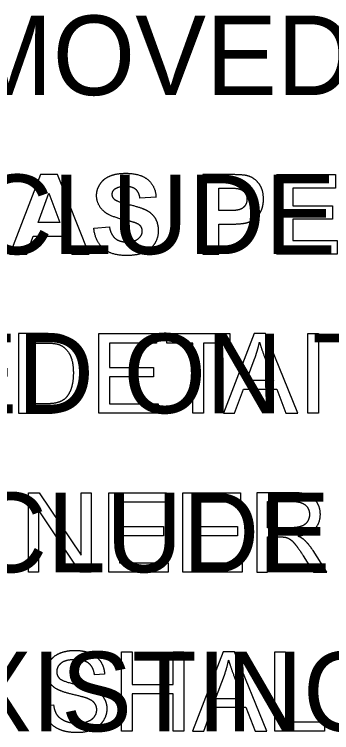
# Model space of a CAD drawing. Extents: x 12316 to 12541, y 1124 to 1850.
# Drawn here: x 12524.754 to 12525.314, y 1787.999 to 1789.263 of the extents above; entities that cross this region are included whole.
import ezdxf

# ---------------------------------------------------------------- set-up
doc = ezdxf.new("R2010")
doc.units = 0
doc.layers.add('SH_Text', color=7, linetype='Continuous')

msp = doc.modelspace()

# ---------------------------------------------------------------- linework, layer by layer
at = {"layer": 'SH_Text'}
for p, q in [((12525.0039, 1788.9412), (12524.9756, 1788.9399)), ((12524.8941, 1788.8868), (12524.9216, 1788.8895)), ((12524.9131, 1788.1018), (12524.8954, 1788.1004)), ((12524.8057, 1788.0462), (12524.8232, 1788.0477))]:
    msp.add_line(p, q, dxfattribs=at)
for points in [[(12524.8862, 1788.8412), (12524.8303, 1788.9812), (12524.8002, 1788.9812), (12524.7458, 1788.8412), (12524.7758, 1788.8412), (12524.7873, 1788.873), (12524.8433, 1788.873), (12524.8554, 1788.8412)], [(12525.2167, 1788.8412), (12525.2167, 1788.9812), (12525.3205, 1788.9812), (12525.3205, 1788.9575), (12525.2449, 1788.9575), (12525.2449, 1788.9264), (12525.3153, 1788.9264), (12525.3153, 1788.9027), (12525.2449, 1788.9027), (12525.2449, 1788.8649), (12525.3232, 1788.8649), (12525.3232, 1788.8412)], [(12524.8342, 1788.8967), (12524.796, 1788.8967), (12524.8149, 1788.9485)], [(12524.9032, 1788.5612), (12524.9032, 1788.7012), (12525.0045, 1788.7012), (12525.0045, 1788.6846), (12524.9217, 1788.6846), (12524.9217, 1788.6418), (12524.9993, 1788.6418), (12524.9993, 1788.6253), (12524.9217, 1788.6253), (12524.9217, 1788.5777), (12525.0077, 1788.5777), (12525.0077, 1788.5612)], [(12525.0689, 1788.5612), (12525.0689, 1788.6846), (12525.0228, 1788.6846), (12525.0228, 1788.7012), (12525.1338, 1788.7012), (12525.1338, 1788.6846), (12525.0874, 1788.6846), (12525.0874, 1788.5612)], [(12525.123, 1788.5612), (12525.1426, 1788.5612), (12525.158, 1788.6035), (12525.2167, 1788.6035), (12525.2329, 1788.5612), (12525.254, 1788.5612), (12525.1968, 1788.7012), (12525.1768, 1788.7012)], [(12525.2719, 1788.5612), (12525.2719, 1788.7012), (12525.2905, 1788.7012), (12525.2905, 1788.5612)], [(12524.7791, 1788.2812), (12524.7791, 1788.4212), (12524.798, 1788.4212), (12524.8717, 1788.3112), (12524.8717, 1788.4212), (12524.8894, 1788.4212), (12524.8894, 1788.2812), (12524.8704, 1788.2812), (12524.7968, 1788.3911), (12524.7968, 1788.2812)], [(12524.9209, 1788.2812), (12524.9209, 1788.4212), (12525.0222, 1788.4212), (12525.0222, 1788.4046), (12524.9394, 1788.4046), (12524.9394, 1788.3618), (12525.017, 1788.3618), (12525.017, 1788.3453), (12524.9394, 1788.3453), (12524.9394, 1788.2977), (12525.0254, 1788.2977), (12525.0254, 1788.2812)], [(12525.0514, 1788.2812), (12525.0514, 1788.4212), (12525.1527, 1788.4212), (12525.1527, 1788.4046), (12525.0699, 1788.4046), (12525.0699, 1788.3618), (12525.1475, 1788.3618), (12525.1475, 1788.3453), (12525.0699, 1788.3453), (12525.0699, 1788.2977), (12525.1559, 1788.2977), (12525.1559, 1788.2812)], [(12524.9433, 1788.0012), (12524.9433, 1788.1412), (12524.9618, 1788.1412), (12524.9618, 1788.0837), (12525.0344, 1788.0837), (12525.0344, 1788.1412), (12525.053, 1788.1412), (12525.053, 1788.0012), (12525.0344, 1788.0012), (12525.0344, 1788.0671), (12524.9618, 1788.0671), (12524.9618, 1788.0012)], [(12525.0685, 1788.0012), (12525.0882, 1788.0012), (12525.1035, 1788.0435), (12525.1623, 1788.0435), (12525.1785, 1788.0012), (12525.1996, 1788.0012), (12525.1424, 1788.1412), (12525.1223, 1788.1412)], [(12525.2136, 1788.0012), (12525.2136, 1788.1412), (12525.2321, 1788.1412), (12525.2321, 1788.0177), (12525.3011, 1788.0177), (12525.3011, 1788.0012)]]:
    msp.add_lwpolyline(points, close=True, dxfattribs=at)
for points in [[(12525.1315, 1788.9812), (12525.0862, 1788.9812), (12525.0862, 1788.8412), (12525.1144, 1788.8412), (12525.1144, 1788.894), (12525.1329, 1788.894)], [(12525.1299, 1788.9177), (12525.1144, 1788.9177), (12525.1144, 1788.9575), (12525.1281, 1788.9575)], [(12524.8097, 1788.7012), (12524.7615, 1788.7012), (12524.7615, 1788.5612), (12524.812, 1788.5612)], [(12524.8099, 1788.5777), (12524.78, 1788.5777), (12524.78, 1788.6846), (12524.8094, 1788.6846)], [(12525.1962, 1788.6575), (12525.2109, 1788.6186), (12525.1633, 1788.6186), (12525.1788, 1788.6597)], [(12525.2439, 1788.4212), (12525.1818, 1788.4212), (12525.1818, 1788.2812), (12525.2003, 1788.2812), (12525.2003, 1788.3434), (12525.2218, 1788.3434)], [(12525.2401, 1788.3594), (12525.2003, 1788.3594), (12525.2003, 1788.4057), (12525.2446, 1788.4057)], [(12525.2633, 1788.3103), (12525.2819, 1788.2812), (12525.305, 1788.2812), (12525.2808, 1788.3193)], [(12525.1418, 1788.0975), (12525.1564, 1788.0586), (12525.1089, 1788.0586), (12525.1244, 1788.0997)]]:
    msp.add_lwpolyline(points, dxfattribs=at)
for points in [[(12524.9052, 1788.9645), (12524.9112, 1788.9738), (12524.9226, 1788.9787)], [(12524.9226, 1788.9787), (12524.9341, 1788.9835), (12524.9502, 1788.9835)], [(12524.9502, 1788.9835), (12524.9766, 1788.9835), (12524.9899, 1788.972)], [(12525.1651, 1788.9791), (12525.1573, 1788.9812), (12525.1315, 1788.9812)], [(12525.1853, 1788.9654), (12525.1772, 1788.9759), (12525.1651, 1788.9791)], [(12524.8991, 1788.9445), (12524.8991, 1788.9552), (12524.9052, 1788.9645)], [(12524.9499, 1788.9602), (12524.9376, 1788.9602), (12524.9306, 1788.9551)], [(12524.9678, 1788.9554), (12524.9618, 1788.9602), (12524.9499, 1788.9602)], [(12524.9899, 1788.972), (12525.0032, 1788.9604), (12525.0039, 1788.9412)], [(12525.1934, 1788.9381), (12525.1934, 1788.9548), (12525.1853, 1788.9654)], [(12524.9306, 1788.9551), (12524.9261, 1788.9518), (12524.9261, 1788.9464)], [(12524.9756, 1788.9399), (12524.9738, 1788.9507), (12524.9678, 1788.9554)], [(12525.1281, 1788.9575), (12525.1434, 1788.9575), (12525.1484, 1788.9565)], [(12525.1484, 1788.9565), (12525.1553, 1788.9553), (12525.1598, 1788.9503)], [(12525.1598, 1788.9503), (12525.1643, 1788.9453), (12525.1643, 1788.9377)], [(12524.912, 1788.9164), (12524.8991, 1788.9279), (12524.8991, 1788.9445)], [(12524.9261, 1788.9464), (12524.9261, 1788.9414), (12524.9303, 1788.9379)], [(12524.9303, 1788.9379), (12524.9357, 1788.9334), (12524.9563, 1788.9285)], [(12525.1643, 1788.9377), (12525.1643, 1788.9315), (12525.1611, 1788.9268)], [(12525.1887, 1788.9164), (12525.1934, 1788.9252), (12525.1934, 1788.9381)], [(12524.9563, 1788.9285), (12524.977, 1788.9237), (12524.9869, 1788.9185)], [(12525.1611, 1788.9268), (12525.1579, 1788.9221), (12525.1522, 1788.9199)], [(12524.9439, 1788.9026), (12524.9212, 1788.9082), (12524.912, 1788.9164)], [(12524.9869, 1788.9185), (12524.9968, 1788.9133), (12525.0024, 1788.9043)], [(12525.1522, 1788.9199), (12525.1466, 1788.9177), (12525.1299, 1788.9177)], [(12525.1768, 1788.9026), (12525.184, 1788.9076), (12525.1887, 1788.9164)], [(12524.9666, 1788.8965), (12524.9616, 1788.8982), (12524.9439, 1788.9026)], [(12524.9768, 1788.8904), (12524.9738, 1788.8939), (12524.9666, 1788.8965)], [(12525.0024, 1788.9043), (12525.0079, 1788.8952), (12525.0079, 1788.882)], [(12525.1622, 1788.896), (12525.1696, 1788.8976), (12525.1768, 1788.9026)], [(12524.9111, 1788.851), (12524.8969, 1788.8633), (12524.8941, 1788.8868)], [(12524.9216, 1788.8895), (12524.9241, 1788.8756), (12524.9317, 1788.8691)], [(12524.9797, 1788.8819), (12524.9797, 1788.8869), (12524.9768, 1788.8904)], [(12525.1329, 1788.894), (12525.1521, 1788.894), (12525.1622, 1788.896)], [(12524.9727, 1788.8684), (12524.9797, 1788.8742), (12524.9797, 1788.8819)], [(12525.0079, 1788.882), (12525.0079, 1788.8699), (12525.0013, 1788.8594)], [(12524.9317, 1788.8691), (12524.9393, 1788.8626), (12524.9522, 1788.8626)], [(12524.9522, 1788.8626), (12524.9658, 1788.8626), (12524.9727, 1788.8684)], [(12525.0013, 1788.8594), (12524.9946, 1788.8489), (12524.9823, 1788.8438)], [(12524.9519, 1788.8387), (12524.9253, 1788.8387), (12524.9111, 1788.851)], [(12524.9823, 1788.8438), (12524.9701, 1788.8387), (12524.9519, 1788.8387)], [(12524.8346, 1788.6992), (12524.826, 1788.7012), (12524.8097, 1788.7012)], [(12524.8552, 1788.6891), (12524.8467, 1788.6964), (12524.8346, 1788.6992)], [(12524.8094, 1788.6846), (12524.8259, 1788.6846), (12524.8334, 1788.6818)], [(12524.8334, 1788.6818), (12524.8437, 1788.6778), (12524.8509, 1788.666)], [(12524.8717, 1788.6652), (12524.8662, 1788.6798), (12524.8552, 1788.6891)], [(12525.1788, 1788.6597), (12525.1835, 1788.673), (12525.1863, 1788.6864)], [(12525.1863, 1788.6864), (12525.1896, 1788.6752), (12525.1962, 1788.6575)], [(12524.8509, 1788.666), (12524.8581, 1788.6542), (12524.8581, 1788.6322)], [(12524.8772, 1788.6319), (12524.8772, 1788.6507), (12524.8717, 1788.6652)], [(12524.8581, 1788.6322), (12524.8581, 1788.6164), (12524.8545, 1788.6053)], [(12524.8735, 1788.6037), (12524.8772, 1788.616), (12524.8772, 1788.6319)], [(12524.8545, 1788.6053), (12524.8508, 1788.5941), (12524.8442, 1788.5875)], [(12524.8639, 1788.5833), (12524.8698, 1788.5914), (12524.8735, 1788.6037)], [(12524.8316, 1788.5803), (12524.8238, 1788.5777), (12524.8099, 1788.5777)], [(12524.8442, 1788.5875), (12524.8395, 1788.5829), (12524.8316, 1788.5803)], [(12524.8512, 1788.5706), (12524.8581, 1788.5752), (12524.8639, 1788.5833)], [(12524.8345, 1788.5636), (12524.8443, 1788.5659), (12524.8512, 1788.5706)], [(12524.812, 1788.5612), (12524.8247, 1788.5612), (12524.8345, 1788.5636)], [(12525.2723, 1788.4174), (12525.2626, 1788.4212), (12525.2439, 1788.4212)], [(12525.2879, 1788.4041), (12525.2821, 1788.4136), (12525.2723, 1788.4174)], [(12525.2446, 1788.4057), (12525.2602, 1788.4057), (12525.2674, 1788.3993)], [(12525.2937, 1788.383), (12525.2937, 1788.3945), (12525.2879, 1788.4041)], [(12525.2674, 1788.3993), (12525.2746, 1788.3929), (12525.2746, 1788.383)], [(12525.2746, 1788.383), (12525.2746, 1788.3762), (12525.2709, 1788.3704)], [(12525.2841, 1788.3579), (12525.2937, 1788.3681), (12525.2937, 1788.383)], [(12525.2709, 1788.3704), (12525.2672, 1788.3646), (12525.26, 1788.362)], [(12525.26, 1788.362), (12525.2528, 1788.3594), (12525.2401, 1788.3594)], [(12525.2543, 1788.3449), (12525.2744, 1788.3476), (12525.2841, 1788.3579)], [(12525.2218, 1788.3434), (12525.229, 1788.3434), (12525.2321, 1788.3427)], [(12525.2321, 1788.3427), (12525.2364, 1788.3417), (12525.2406, 1788.339)], [(12525.2655, 1788.3379), (12525.2616, 1788.3413), (12525.2543, 1788.3449)], [(12525.2406, 1788.339), (12525.2447, 1788.3363), (12525.25, 1788.3296)], [(12525.25, 1788.3296), (12525.2552, 1788.3229), (12525.2633, 1788.3103)], [(12525.2808, 1788.3193), (12525.2736, 1788.3305), (12525.2655, 1788.3379)], [(12524.817, 1788.1248), (12524.823, 1788.1341), (12524.8346, 1788.1388)], [(12524.8346, 1788.1388), (12524.8462, 1788.1436), (12524.8603, 1788.1436)], [(12524.8603, 1788.1436), (12524.8759, 1788.1436), (12524.8879, 1788.1386)], [(12524.8879, 1788.1386), (12524.8998, 1788.1336), (12524.9062, 1788.1239)], [(12524.811, 1788.105), (12524.811, 1788.1156), (12524.817, 1788.1248)], [(12524.8611, 1788.1273), (12524.8442, 1788.1273), (12524.8365, 1788.1211)], [(12524.8856, 1788.1205), (12524.8773, 1788.1273), (12524.8611, 1788.1273)], [(12525.1244, 1788.0997), (12525.1291, 1788.113), (12525.1319, 1788.1264)], [(12525.1319, 1788.1264), (12525.1352, 1788.1152), (12525.1418, 1788.0975)], [(12524.8365, 1788.1211), (12524.8288, 1788.115), (12524.8288, 1788.1063)], [(12524.8954, 1788.1004), (12524.8939, 1788.1137), (12524.8856, 1788.1205)], [(12524.9062, 1788.1239), (12524.9126, 1788.1141), (12524.9131, 1788.1018)], [(12524.8159, 1788.0876), (12524.811, 1788.0954), (12524.811, 1788.105)], [(12524.8288, 1788.1063), (12524.8288, 1788.0987), (12524.8343, 1788.0938)], [(12524.8308, 1788.0745), (12524.8208, 1788.0798), (12524.8159, 1788.0876)], [(12524.8343, 1788.0938), (12524.8396, 1788.089), (12524.8623, 1788.0839)], [(12524.858, 1788.0658), (12524.8386, 1788.0704), (12524.8308, 1788.0745)], [(12524.8623, 1788.0839), (12524.885, 1788.0787), (12524.8934, 1788.0749)], [(12524.8934, 1788.0749), (12524.9056, 1788.0693), (12524.9114, 1788.0606)], [(12524.883, 1788.059), (12524.8773, 1788.0612), (12524.858, 1788.0658)], [(12524.8956, 1788.0507), (12524.8918, 1788.0556), (12524.883, 1788.059)], [(12524.8994, 1788.0392), (12524.8994, 1788.0458), (12524.8956, 1788.0507)], [(12524.9114, 1788.0606), (12524.9172, 1788.052), (12524.9172, 1788.0407)], [(12524.8134, 1788.021), (12524.8061, 1788.0322), (12524.8057, 1788.0462)], [(12524.8232, 1788.0477), (12524.8245, 1788.0372), (12524.829, 1788.0304)], [(12524.8955, 1788.0272), (12524.8994, 1788.0327), (12524.8994, 1788.0392)], [(12524.9172, 1788.0407), (12524.9172, 1788.0296), (12524.9108, 1788.0197)], [(12524.829, 1788.0304), (12524.8336, 1788.0237), (12524.8431, 1788.0195)], [(12524.8834, 1788.0185), (12524.8915, 1788.0217), (12524.8955, 1788.0272)], [(12524.8336, 1788.0044), (12524.8207, 1788.0099), (12524.8134, 1788.021)], [(12524.8431, 1788.0195), (12524.8527, 1788.0154), (12524.8646, 1788.0154)], [(12524.8646, 1788.0154), (12524.8752, 1788.0154), (12524.8834, 1788.0185)], [(12524.9108, 1788.0197), (12524.9044, 1788.0098), (12524.8924, 1788.0043)], [(12524.8655, 1787.9988), (12524.8464, 1787.9988), (12524.8336, 1788.0044)], [(12524.8924, 1788.0043), (12524.8805, 1787.9988), (12524.8655, 1787.9988)]]:
    msp.add_open_spline(points, degree=2, dxfattribs=at)

# ---------------------------------------------------------------- texts
for s, p in [('ITEM 201 - TREE REMOVED, 30":', (12522.8764, 1789.1212)), ('THIS ITEM SHALL INCLUDE THE COMPLETE REMOVAL OF EXISTING ', (12522.8764, 1788.8412)), ('TREE(S) AS DETAILED ON TYPICAL DETAIL SHEET         .  THE ', (12522.8764, 1788.5612)), ('REMOVAL SHALL INCLUDE STUMP REMOVAL TO A MINIMUM DEPTH ', (12522.8764, 1788.2812)), ("OF 1' BELOW THE EXISTING GROUND SURFACE.", (12522.8764, 1788.0012))]:
    msp.add_text(s, height=0.14, dxfattribs=at).set_placement(p)

doc.saveas('drawing.dxf')
